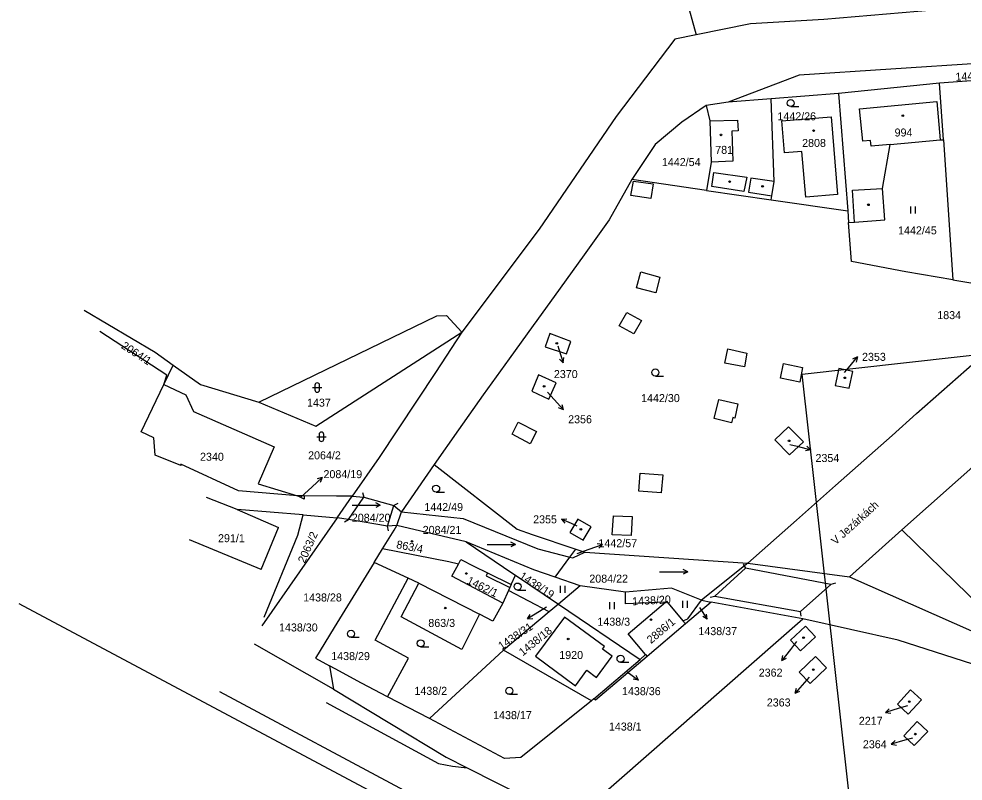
# Model space of a CAD drawing. Extents: x -794765 to -785424, y -1118958 to -1108731.
# Drawn here: x -792987.4 to -792786.8, y -1110324.3 to -1110162.4 of the extents above; entities that cross this region are included whole.
import ezdxf

# ---------------------------------------------------------------- set-up
doc = ezdxf.new("R2010")
doc.units = 0
for name, color, linetype in [('Level 66', 7, 'Continuous'), ('Level 71', 7, 'Continuous'), ('Level 75', 7, 'Continuous'), ('Level 76', 7, 'Continuous'), ('Level 77', 7, 'Continuous'), ('Level 79', 7, 'Continuous'), ('Level 80', 7, 'Continuous')]:
    doc.layers.add(name, color=color, linetype=linetype)

msp = doc.modelspace()

# ---------------------------------------------------------------- linework, layer by layer
at = {"layer": 'Level 66'}
for p, q in [((-792823.41, -1110181), (-792821.66, -1110181)), ((-792797.88, -1110203.74), (-792797.88, -1110202.24)), ((-792796.88, -1110203.74), (-792796.88, -1110202.24)), ((-792852.17, -1110238.22), (-792850.42, -1110238.22)), ((-792925.01, -1110240.68), (-792923.01, -1110240.68)), ((-792924.51, -1110240.18), (-792924.51, -1110241.18)), ((-792923.51, -1110241.18), (-792923.51, -1110240.18)), ((-792924.13, -1110251.13), (-792922.13, -1110251.13)), ((-792923.63, -1110250.63), (-792923.63, -1110251.63)), ((-792922.63, -1110251.63), (-792922.63, -1110250.63)), ((-792898.75, -1110262.89), (-792897, -1110262.89)), ((-792916.61, -1110265.68), (-792910.61, -1110265.68)), ((-792910.61, -1110265.68), (-792911.59, -1110265.18)), ((-792910.61, -1110265.68), (-792911.59, -1110266.18)), ((-792887.91, -1110274), (-792881.91, -1110274)), ((-792881.91, -1110274), (-792882.89, -1110273.5)), ((-792881.91, -1110274), (-792882.89, -1110274.5)), ((-792851.3, -1110279.84), (-792845.3, -1110279.84)), ((-792845.3, -1110279.84), (-792846.28, -1110279.34)), ((-792845.3, -1110279.84), (-792846.28, -1110280.34)), ((-792881.44, -1110283.69), (-792879.69, -1110283.69)), ((-792872.3, -1110284.28), (-792872.3, -1110282.78)), ((-792871.3, -1110284.28), (-792871.3, -1110282.78)), ((-792861.86, -1110287.77), (-792861.86, -1110286.27)), ((-792860.86, -1110287.77), (-792860.86, -1110286.27)), ((-792846.36, -1110287.47), (-792846.36, -1110285.97)), ((-792845.36, -1110287.47), (-792845.36, -1110285.97)), ((-792916.83, -1110293.72), (-792915.08, -1110293.72)), ((-792902.05, -1110295.76), (-792900.3, -1110295.76)), ((-792859.57, -1110299.03), (-792857.82, -1110299.03)), ((-792883.19, -1110305.83), (-792881.44, -1110305.83))]:
    msp.add_line(p, q, dxfattribs=at)
for centre in [(-792823.41, -1110180.25), (-792852.17, -1110237.47), (-792898.75, -1110262.14), (-792881.44, -1110282.94), (-792916.83, -1110292.97), (-792902.05, -1110295.01), (-792859.57, -1110298.28), (-792883.19, -1110305.08)]:
    msp.add_circle(centre, 0.75, dxfattribs=at)
for centre, start, end in [((-792924.01, -1110240.18), 0, 180), ((-792924.01, -1110241.18), 180, 359.9879), ((-792923.13, -1110250.63), 0, 180), ((-792923.13, -1110251.63), 180, 359.9879)]:
    msp.add_arc(centre, 0.5, start, end, dxfattribs=at)
at = {"layer": 'Level 71'}
msp.add_lwpolyline([(-792522.06, -1110204.41), (-792422.02, -1111099.6), (-792720.93, -1111133), (-792820.96, -1110237.81)], close=True, dxfattribs=at)
at = {"layer": 'Level 75'}
for p, q in [((-792845.9, -1110157.04), (-792843.51, -1110165.75)), ((-792765.3, -1110173.93), (-792791.78, -1110176.05)), ((-792791.78, -1110176.05), (-792813.29, -1110178.21)), ((-792790.97, -1110188.03), (-792791.78, -1110176.05)), ((-792827.55, -1110179.32), (-792836.73, -1110180.03)), ((-792813.29, -1110178.21), (-792827.55, -1110179.32)), ((-792813.29, -1110178.21), (-792811.29, -1110203.16)), ((-792836.73, -1110180.03), (-792841.38, -1110180.79)), ((-792790.97, -1110188.03), (-792788.97, -1110217.76)), ((-792841.32, -1110198.79), (-792857.15, -1110196.49)), ((-792841.32, -1110198.79), (-792827.6, -1110200.79)), ((-792827.6, -1110200.79), (-792811.29, -1110203.16)), ((-792811.29, -1110203.16), (-792811.1, -1110205.6)), ((-792788.97, -1110217.76), (-792768.39, -1110221.23)), ((-792973.54, -1110224.23), (-792958.48, -1110233.18)), ((-792958.48, -1110233.18), (-792954.6, -1110235.91)), ((-792956.62, -1110240.06), (-792954.6, -1110235.91)), ((-792954.6, -1110235.91), (-792948.79, -1110240.01)), ((-792956.62, -1110240.06), (-792951.92, -1110242.23)), ((-792948.79, -1110240.01), (-792936.43, -1110243.76)), ((-792769.54, -1110244.05), (-792799.79, -1110270.88)), ((-792899.17, -1110257.02), (-792906.12, -1110267.05)), ((-792926.76, -1110263.67), (-792928.23, -1110263.66)), ((-792919.79, -1110268.32), (-792916.57, -1110263.77)), ((-792907.12, -1110270), (-792906.12, -1110267.05)), ((-792919.79, -1110268.32), (-792935.78, -1110291.3)), ((-792892.36, -1110273.46), (-792907.12, -1110270)), ((-792810.95, -1110280.9), (-792799.79, -1110270.88)), ((-792911.93, -1110277.84), (-792910.16, -1110274.96)), ((-792870.31, -1110276.7), (-792869.04, -1110275)), ((-792869.04, -1110275), (-792867.13, -1110275.64)), ((-792867.13, -1110275.64), (-792832.52, -1110277.99)), ((-792904.66, -1110281.18), (-792911.93, -1110277.84)), ((-792873.47, -1110280.93), (-792870.31, -1110276.7)), ((-792832.52, -1110277.99), (-792842.37, -1110285.86)), ((-792832.52, -1110277.99), (-792810.95, -1110280.9)), ((-792882.78, -1110282.53), (-792881.86, -1110280.55)), ((-792881.86, -1110280.55), (-792872.78, -1110286.68)), ((-792868.13, -1110282.78), (-792873.47, -1110280.93)), ((-792883.35, -1110283.75), (-792884.61, -1110286.45)), ((-792874.76, -1110288.34), (-792883.35, -1110283.75)), ((-792868.13, -1110282.78), (-792872.78, -1110286.68)), ((-792858.5, -1110284.12), (-792868.13, -1110282.78)), ((-792840.31, -1110286.24), (-792845.77, -1110290.89)), ((-792842.37, -1110285.86), (-792840.31, -1110286.24)), ((-792820.87, -1110289.8), (-792840.31, -1110286.24)), ((-792872.78, -1110286.68), (-792874.76, -1110288.34)), ((-792872.78, -1110286.68), (-792855.41, -1110298.4)), ((-792874.76, -1110288.34), (-792884.46, -1110296.46)), ((-792845.77, -1110290.89), (-792846.34, -1110290.21)), ((-792845.77, -1110290.89), (-792853.89, -1110297.81)), ((-792920.52, -1110304.75), (-792937.34, -1110295.19)), ((-792924.39, -1110298.18), (-792921.42, -1110299.79)), ((-792884.46, -1110296.46), (-792900.15, -1110310.99)), ((-792865.76, -1110307.22), (-792884.46, -1110296.46)), ((-792853.89, -1110297.81), (-792864.87, -1110307.09)), ((-792855.41, -1110298.4), (-792854.27, -1110297.36)), ((-792854.27, -1110297.36), (-792853.89, -1110297.81)), ((-792921.42, -1110299.79), (-792920.52, -1110304.75)), ((-792865.22, -1110306.76), (-792855.41, -1110298.4)), ((-792900.15, -1110310.99), (-792909.06, -1110306.37)), ((-792865.22, -1110306.76), (-792865.76, -1110307.22)), ((-792864.87, -1110307.09), (-792865.22, -1110306.76))]:
    msp.add_line(p, q, dxfattribs=at)
for points in [[(-792793.11, -1110160.53), (-792816.41, -1110162.52), (-792831.95, -1110163.4), (-792843.51, -1110165.75)], [(-792843.51, -1110165.75), (-792848, -1110166.66), (-792860.5, -1110183.08), (-792876.83, -1110207.04), (-792893.29, -1110228.94)], [(-792724.21, -1110167.98), (-792821.65, -1110174.35), (-792836.73, -1110180.03)], [(-792827.6, -1110200.79), (-792827.45, -1110199.93), (-792826.92, -1110196.88), (-792827.55, -1110179.32)], [(-792841.38, -1110180.79), (-792846.53, -1110184.28), (-792852.19, -1110189.06), (-792857.15, -1110196.49)], [(-792841.38, -1110180.79), (-792840.6, -1110183.99), (-792840.3, -1110192.79), (-792841.32, -1110198.79)], [(-792813.45, -1110199.69), (-792820.2, -1110200.26), (-792821.03, -1110190.53), (-792824.71, -1110190.8), (-792825.3, -1110184.04), (-792814.83, -1110183.14), (-792813.45, -1110199.69)], [(-792811.1, -1110205.6), (-792809.89, -1110205.52), (-792803.4, -1110205.05), (-792803.88, -1110198.43), (-792802.3, -1110189.05), (-792791.66, -1110188.09), (-792790.97, -1110188.03)], [(-792857.15, -1110196.49), (-792861.96, -1110205.07), (-792867.33, -1110212.5), (-792872.43, -1110219.57), (-792877.35, -1110226.4), (-792878.15, -1110227.5), (-792883.23, -1110234.55), (-792888.74, -1110242.19), (-792893.98, -1110249.64), (-792899.17, -1110257.02)], [(-792788.97, -1110217.76), (-792798.95, -1110216.07), (-792810.47, -1110213.88), (-792811.1, -1110205.6)], [(-792832.52, -1110277.99), (-792822.21, -1110268.85), (-792813.91, -1110261.49), (-792801.89, -1110250.87), (-792796.66, -1110246.15), (-792768.39, -1110221.23)], [(-792936.43, -1110243.76), (-792898.61, -1110225.41), (-792896.52, -1110225.36), (-792893.29, -1110228.94)], [(-792956.62, -1110240.06), (-792955.98, -1110238.02), (-792970.23, -1110228.78)], [(-792936.43, -1110243.76), (-792924.34, -1110248.84), (-792893.29, -1110228.94)], [(-792893.29, -1110228.94), (-792898.91, -1110237.46), (-792910.83, -1110255.53), (-792916.57, -1110263.77)], [(-792874.62, -1110229.22), (-792875.6, -1110231.99), (-792871.07, -1110233.51), (-792870.1, -1110230.91), (-792874.62, -1110229.22)], [(-792874.8, -1110243.12), (-792873.23, -1110239.68), (-792876.98, -1110237.97), (-792878.45, -1110241.45), (-792874.8, -1110243.12)], [(-792813.99, -1110240.21), (-792811, -1110240.77), (-792810.21, -1110237.29), (-792813.21, -1110236.61), (-792813.99, -1110240.21)], [(-792928.23, -1110263.66), (-792940.73, -1110262.6), (-792953.02, -1110256.95), (-792953, -1110257.24), (-792958.43, -1110255.07), (-792958.74, -1110251.34), (-792961.42, -1110250.11), (-792956.62, -1110240.06)], [(-792951.92, -1110242.23), (-792950.31, -1110245.78), (-792933.18, -1110253.25), (-792936.55, -1110261.13), (-792928.23, -1110263.66)], [(-792823.85, -1110248.99), (-792826.77, -1110251.75), (-792823.7, -1110254.99), (-792820.68, -1110252.18), (-792823.85, -1110248.99)], [(-792899.17, -1110257.02), (-792881.53, -1110270.73), (-792878.38, -1110271.88), (-792869.04, -1110275)], [(-792927.02, -1110267.74), (-792941.03, -1110266.61), (-792947.55, -1110264.05)], [(-792926.76, -1110263.67), (-792926.8, -1110264.36), (-792928.23, -1110263.66)], [(-792916.57, -1110263.77), (-792919.91, -1110263.74), (-792926.76, -1110263.67)], [(-792916.57, -1110263.77), (-792914.11, -1110263.94), (-792907.75, -1110265.75), (-792906.12, -1110267.05)], [(-792935.32, -1110289.46), (-792928.14, -1110272.02), (-792927.02, -1110267.74)], [(-792927.02, -1110267.74), (-792921.4, -1110268.19), (-792919.79, -1110268.32)], [(-792906.12, -1110267.05), (-792893, -1110268.51), (-792877.11, -1110274.91), (-792870.31, -1110276.7)], [(-792907.12, -1110270), (-792909.08, -1110270.11), (-792917.38, -1110268.7), (-792919.79, -1110268.32)], [(-792910.16, -1110274.96), (-792907.69, -1110270.93), (-792907.12, -1110270)], [(-792867.49, -1110273.06), (-792865.84, -1110270.25), (-792868.65, -1110268.61), (-792870.36, -1110271.49), (-792867.49, -1110273.06)], [(-792799.79, -1110270.88), (-792785.68, -1110284.61), (-792780.46, -1110289.67), (-792774.1, -1110287.81), (-792768.98, -1110283.36), (-792748.68, -1110294.88)], [(-792892.36, -1110273.46), (-792882.45, -1110280.15), (-792881.86, -1110280.55)], [(-792873.47, -1110280.93), (-792877.98, -1110279.37), (-792892.36, -1110273.46)], [(-792894.02, -1110278.16), (-792896.04, -1110277.71), (-792910.16, -1110274.96)], [(-792870.31, -1110276.7), (-792869.7, -1110276.86), (-792867.13, -1110275.64)], [(-792911.93, -1110277.84), (-792920.4, -1110291.66), (-792924.39, -1110298.18)], [(-792884.61, -1110286.45), (-792895.4, -1110280.77), (-792894.02, -1110278.16)], [(-792894.02, -1110278.16), (-792893.53, -1110277.23), (-792890.72, -1110278.62), (-792887.81, -1110280.05), (-792882.78, -1110282.53)], [(-792909.06, -1110306.37), (-792904.65, -1110298.12), (-792911.69, -1110294.36), (-792904.66, -1110281.18)], [(-792884.61, -1110286.45), (-792886.72, -1110290.26), (-792889.5, -1110288.84), (-792893.29, -1110296.28), (-792896.99, -1110294.3), (-792906.21, -1110289.36), (-792902.39, -1110282.23), (-792904.66, -1110281.18)], [(-792810.95, -1110280.9), (-792780.07, -1110294.56), (-792755.03, -1110302.83), (-792738.35, -1110319.04), (-792720.66, -1110333.41), (-792681.61, -1110364.96), (-792649.52, -1110392.89)], [(-792882.78, -1110282.53), (-792883.08, -1110283.17), (-792883.35, -1110283.75)], [(-792850.04, -1110286.28), (-792858.54, -1110286.62), (-792858.5, -1110284.12)], [(-792842.37, -1110285.86), (-792848.73, -1110283.28), (-792858.5, -1110284.12)], [(-792854.27, -1110297.36), (-792857.96, -1110292.98), (-792850.04, -1110286.28)], [(-792850.04, -1110286.28), (-792849.81, -1110286.08), (-792846.34, -1110290.21)], [(-792846.34, -1110290.21), (-792845.29, -1110289.77), (-792842.37, -1110285.86)], [(-792987.4, -1110286.52), (-792903.63, -1110331.24), (-792901.83, -1110335.69)], [(-792863.41, -1110296.26), (-792863, -1110295.7), (-792871.48, -1110289.47), (-792877.63, -1110297.71), (-792869.11, -1110304.01), (-792866.7, -1110300.73)], [(-792861.96, -1110336.71), (-792864.51, -1110333.18), (-792865.03, -1110328.55), (-792820.87, -1110289.8)], [(-792614.4, -1110416.41), (-792624.78, -1110416.77), (-792634.65, -1110411.27), (-792666.12, -1110385.5), (-792684.9, -1110369.28), (-792739.95, -1110324.15), (-792759.16, -1110307.61), (-792800.59, -1110294.35), (-792820.87, -1110289.8)], [(-792821.33, -1110296.58), (-792818.18, -1110293.63), (-792820.28, -1110291.38), (-792823.43, -1110294.34), (-792821.33, -1110296.58)], [(-792866.7, -1110300.73), (-792864.66, -1110302.23), (-792861.37, -1110297.76), (-792863.41, -1110296.26)], [(-792819.27, -1110303.52), (-792815.84, -1110300.19), (-792818.18, -1110297.78), (-792821.61, -1110301.11), (-792819.27, -1110303.52)], [(-792909.06, -1110306.37), (-792914.61, -1110303.49), (-792920.21, -1110300.45), (-792921.42, -1110299.79)], [(-792920.52, -1110304.75), (-792896.6, -1110319.19), (-792892.13, -1110321.45), (-792866.5, -1110334.41), (-792861.96, -1110336.71)], [(-792795.65, -1110307), (-792797.95, -1110304.89), (-792800.73, -1110307.93), (-792798.43, -1110310.03), (-792795.65, -1110307)], [(-792865.76, -1110307.22), (-792880.76, -1110319.28), (-792884.2, -1110319.45), (-792900.15, -1110310.99)], [(-792794.31, -1110313.72), (-792796.53, -1110311.62), (-792799.38, -1110314.63), (-792797.16, -1110316.73), (-792794.31, -1110313.72)]]:
    msp.add_lwpolyline(points, dxfattribs=at)
at = {"layer": 'Level 77'}
for p, q in [((-792808.83, -1110181.45), (-792792.4, -1110179.95)), ((-792792.4, -1110179.95), (-792791.66, -1110188.09)), ((-792808.1, -1110188.37), (-792808.83, -1110181.45)), ((-792840.6, -1110183.99), (-792834.75, -1110183.87)), ((-792834.75, -1110183.87), (-792834.58, -1110186.16)), ((-792834.58, -1110186.16), (-792835.89, -1110186.25)), ((-792835.89, -1110186.25), (-792835.7, -1110192.61)), ((-792806.46, -1110188.19), (-792808.1, -1110188.37)), ((-792806.34, -1110189.41), (-792806.46, -1110188.19)), ((-792802.3, -1110189.05), (-792806.34, -1110189.41)), ((-792835.7, -1110192.61), (-792840.3, -1110192.79)), ((-792840.2, -1110197.95), (-792839.77, -1110194.99)), ((-792839.77, -1110194.99), (-792832.76, -1110196.02)), ((-792832.76, -1110196.02), (-792833.34, -1110199.02)), ((-792857.35, -1110199.89), (-792856.8, -1110196.81)), ((-792856.8, -1110196.81), (-792852.66, -1110197.4)), ((-792852.66, -1110197.4), (-792853.13, -1110200.52)), ((-792833.34, -1110199.02), (-792840.2, -1110197.95)), ((-792831.86, -1110196.19), (-792832.4, -1110199.16)), ((-792826.92, -1110196.88), (-792831.86, -1110196.19)), ((-792853.13, -1110200.52), (-792857.35, -1110199.89)), ((-792832.4, -1110199.16), (-792827.45, -1110199.93)), ((-792810.29, -1110198.78), (-792803.88, -1110198.43)), ((-792809.89, -1110205.52), (-792810.29, -1110198.78)), ((-792856.16, -1110219.49), (-792855.29, -1110216.11)), ((-792855.29, -1110216.11), (-792851.2, -1110217.2)), ((-792851.2, -1110217.2), (-792852.08, -1110220.56)), ((-792852.08, -1110220.56), (-792856.16, -1110219.49)), ((-792859.83, -1110227.54), (-792858.25, -1110224.71)), ((-792858.25, -1110224.71), (-792855.15, -1110226.43)), ((-792856.73, -1110229.27), (-792859.83, -1110227.54)), ((-792855.15, -1110226.43), (-792856.73, -1110229.27)), ((-792837.43, -1110235.48), (-792836.76, -1110232.44)), ((-792836.76, -1110232.44), (-792832.7, -1110233.35)), ((-792832.7, -1110233.35), (-792833.26, -1110236.25)), ((-792833.26, -1110236.25), (-792837.43, -1110235.48)), ((-792825.57, -1110238.69), (-792824.93, -1110235.56)), ((-792824.93, -1110235.56), (-792820.88, -1110236.41)), ((-792820.88, -1110236.41), (-792821.5, -1110239.52)), ((-792821.5, -1110239.52), (-792825.57, -1110238.69)), ((-792839.7, -1110247.27), (-792838.69, -1110243.18)), ((-792838.69, -1110243.18), (-792834.64, -1110244.14)), ((-792834.64, -1110244.14), (-792835.31, -1110247.16)), ((-792882.6, -1110250.56), (-792881.34, -1110248.01)), ((-792881.34, -1110248.01), (-792877.43, -1110250)), ((-792835.97, -1110248.19), (-792839.7, -1110247.27)), ((-792835.69, -1110247.06), (-792835.97, -1110248.19)), ((-792835.31, -1110247.16), (-792835.69, -1110247.06)), ((-792877.43, -1110250), (-792878.75, -1110252.61)), ((-792878.75, -1110252.61), (-792882.6, -1110250.56)), ((-792855.65, -1110262.71), (-792855.41, -1110258.83)), ((-792855.41, -1110258.83), (-792850.59, -1110259.23)), ((-792850.59, -1110259.23), (-792850.91, -1110263.04)), ((-792917.38, -1110268.7), (-792914.11, -1110263.94)), ((-792914.42, -1110262.99), (-792914.11, -1110263.94)), ((-792850.91, -1110263.04), (-792855.65, -1110262.71)), ((-792909.08, -1110270.11), (-792907.75, -1110265.75)), ((-792906.88, -1110265.27), (-792907.75, -1110265.75)), ((-792941.03, -1110266.61), (-792932.22, -1110270.38)), ((-792861.34, -1110271.93), (-792861.09, -1110267.89)), ((-792861.09, -1110267.89), (-792857.12, -1110268.09)), ((-792857.12, -1110268.09), (-792857.32, -1110272.1)), ((-792918.23, -1110269.23), (-792917.38, -1110268.7)), ((-792908.84, -1110271.08), (-792909.08, -1110270.11)), ((-792935.89, -1110279.29), (-792932.22, -1110270.38)), ((-792857.32, -1110272.1), (-792861.34, -1110271.93)), ((-792935.89, -1110279.29), (-792951.18, -1110272.99)), ((-792833.52, -1110278.2), (-792833, -1110279.06)), ((-792887.81, -1110280.05), (-792888.12, -1110280.67)), ((-792833, -1110279.06), (-792839.55, -1110285.01)), ((-792814.88, -1110282.54), (-792833, -1110279.06)), ((-792902.39, -1110282.23), (-792889.5, -1110288.84)), ((-792888.12, -1110280.67), (-792883.08, -1110283.17)), ((-792813.93, -1110282.22), (-792814.88, -1110282.54)), ((-792821.32, -1110288.22), (-792814.88, -1110282.54)), ((-792840.53, -1110285.22), (-792839.55, -1110285.01)), ((-792839.55, -1110285.01), (-792821.32, -1110288.22)), ((-792821.18, -1110289.21), (-792821.32, -1110288.22)), ((-792944.81, -1110305.21), (-792903.48, -1110327.29)), ((-792922.09, -1110307.54), (-792898.28, -1110320.5)), ((-792898.28, -1110320.5), (-792895.24, -1110321.1)), ((-792895.24, -1110321.1), (-792892.13, -1110321.45))]:
    msp.add_line(p, q, dxfattribs=at)
at = {"layer": 'Level 79'}
for centre in [(-792799.59, -1110182.93), (-792818.54, -1110186.11), (-792838.22, -1110187.01), (-792836.4, -1110196.93), (-792829.4, -1110197.95), (-792806.89, -1110201.86), (-792873.12, -1110231.28), (-792811.93, -1110238.61), (-792875.8, -1110240.43), (-792823.75, -1110251.99), (-792867.99, -1110270.79), (-792903.86, -1110273.34), (-792892.32, -1110280.17), (-792896.81, -1110287.5), (-792853.11, -1110289.97), (-792870.68, -1110294.08), (-792820.69, -1110293.81), (-792818.61, -1110300.58), (-792798.22, -1110307.39), (-792796.95, -1110314.29)]:
    msp.add_circle(centre, 0.175, dxfattribs=at)
at = {"layer": 'Level 80'}
for p, q in [((-792872.92, -1110231.83), (-792872.68, -1110232.55)), ((-792872.68, -1110232.55), (-792871.75, -1110235.4)), ((-792871.75, -1110235.4), (-792872.54, -1110234.61)), ((-792871.75, -1110235.4), (-792871.59, -1110234.3)), ((-792811.14, -1110236.49), (-792809.25, -1110234.16)), ((-792809.25, -1110234.16), (-792810.27, -1110234.62)), ((-792809.25, -1110234.16), (-792809.49, -1110235.25)), ((-792811.96, -1110237.5), (-792811.14, -1110236.49)), ((-792875.08, -1110241.63), (-792873.69, -1110243.19)), ((-792873.69, -1110243.19), (-792871.68, -1110245.42)), ((-792871.68, -1110245.42), (-792872.72, -1110245.01)), ((-792871.68, -1110245.42), (-792871.98, -1110244.34)), ((-792823.62, -1110252.74), (-792822.06, -1110253.14)), ((-792822.06, -1110253.14), (-792819.15, -1110253.87)), ((-792819.15, -1110253.87), (-792820.24, -1110254.11)), ((-792819.15, -1110253.87), (-792820, -1110253.14)), ((-792925.18, -1110261.82), (-792922.98, -1110259.77)), ((-792922.98, -1110259.77), (-792924.06, -1110260.09)), ((-792922.98, -1110259.77), (-792923.38, -1110260.82)), ((-792927.41, -1110263.89), (-792925.18, -1110261.82)), ((-792872.12, -1110268.66), (-792871.01, -1110268.59)), ((-792869.36, -1110269.83), (-792872.12, -1110268.66)), ((-792872.12, -1110268.66), (-792871.4, -1110269.51)), ((-792868.75, -1110270.08), (-792869.36, -1110269.83)), ((-792866.25, -1110275.03), (-792863.43, -1110274)), ((-792863.43, -1110274), (-792864.54, -1110273.88)), ((-792863.43, -1110274), (-792864.2, -1110274.82)), ((-792868.77, -1110275.95), (-792866.25, -1110275.03)), ((-792876.79, -1110288.23), (-792879.33, -1110289.82)), ((-792875.31, -1110287.31), (-792876.79, -1110288.23)), ((-792842.78, -1110287.38), (-792841.15, -1110289.9)), ((-792879.33, -1110289.82), (-792878.75, -1110288.86)), ((-792879.33, -1110289.82), (-792878.22, -1110289.71)), ((-792841.15, -1110289.9), (-792842.11, -1110289.33)), ((-792841.15, -1110289.9), (-792841.27, -1110288.78)), ((-792823.47, -1110296.29), (-792825.32, -1110298.66)), ((-792822.17, -1110294.61), (-792823.47, -1110296.29)), ((-792825.32, -1110298.66), (-792825.1, -1110297.56)), ((-792825.32, -1110298.66), (-792824.31, -1110298.17)), ((-792858.17, -1110301.04), (-792855.77, -1110302.85)), ((-792855.77, -1110302.85), (-792856.27, -1110301.84)), ((-792819.5, -1110302.17), (-792820.51, -1110303.32)), ((-792855.77, -1110302.85), (-792856.87, -1110302.64)), ((-792820.51, -1110303.32), (-792822.48, -1110305.58)), ((-792822.48, -1110305.58), (-792822.2, -1110304.5)), ((-792822.48, -1110305.58), (-792821.44, -1110305.16)), ((-792798.63, -1110308.25), (-792800.4, -1110308.79)), ((-792800.4, -1110308.79), (-792803.27, -1110309.67)), ((-792803.27, -1110309.67), (-792802.46, -1110308.9)), ((-792803.27, -1110309.67), (-792802.17, -1110309.85)), ((-792799.19, -1110315.6), (-792802.08, -1110316.43)), ((-792802.08, -1110316.43), (-792801.25, -1110315.67)), ((-792797.52, -1110315.11), (-792799.19, -1110315.6)), ((-792802.08, -1110316.43), (-792800.97, -1110316.63))]:
    msp.add_line(p, q, dxfattribs=at)

# ---------------------------------------------------------------- texts
at = {"layer": 'Level 76'}
for s, rotation, p in [('1442/51', 3, (-792788.36, -1110175.52)), ('2064/1', 327, (-792965.79, -1110232.21)), ('2063/2', 66, (-792926.66, -1110278.11)), ('863/4', 349, (-792907.3, -1110274.77)), ('1438/19', 327, (-792881.25, -1110281.12)), ('1462/1', 334, (-792892.38, -1110282.23)), ('1438/20', 3, (-792857.05, -1110286.93)), ('2886/1', 40, (-792853.1, -1110295.18)), ('1438/31', 34, (-792884.84, -1110296.46)), ('1438/18', 39, (-792880.33, -1110297.78))]:
    msp.add_text(s, height=1.7, rotation=rotation, dxfattribs=at).set_placement(p)
for s, p in [('1442/26', (-792826.24, -1110183.91)), ('994', (-792801.34, -1110187.35)), ('2808', (-792820.99, -1110189.57)), ('781', (-792839.45, -1110191.04)), ('1442/54', (-792850.78, -1110193.63)), ('1442/45', (-792800.6, -1110208.14)), ('1834', (-792792.28, -1110226.14)), ('2353', (-792808.26, -1110235)), ('2370', (-792873.73, -1110238.66)), ('1442/30', (-792855.2, -1110243.76)), ('1437', (-792926.18, -1110244.73)), ('2356', (-792870.7, -1110248.26)), ('2064/2', (-792925.95, -1110255.92)), ('2340', (-792948.91, -1110256.22)), ('2354', (-792818.15, -1110256.49)), ('2084/19', (-792922.68, -1110259.92)), ('1442/49', (-792901.25, -1110266.9)), ('2084/20', (-792916.66, -1110269.17)), ('2355', (-792878.14, -1110269.52)), ('2084/21', (-792901.6, -1110271.76)), ('291/1', (-792945.09, -1110273.52)), ('1442/57', (-792864.26, -1110274.58)), ('2084/22', (-792866.2, -1110282.11)), ('1438/28', (-792927, -1110286.11)), ('863/3', (-792900.41, -1110291.52)), ('1438/3', (-792864.49, -1110291.26)), ('1438/30', (-792932.13, -1110292.48)), ('1438/37', (-792843.03, -1110293.26)), ('1438/29', (-792921.04, -1110298.56)), ('1920', (-792872.59, -1110298.33)), ('2362', (-792830.21, -1110302.07)), ('1438/2', (-792903.36, -1110305.94)), ('1438/36', (-792859.26, -1110306.01)), ('2363', (-792828.5, -1110308.41)), ('1438/17', (-792886.64, -1110311.1)), ('1438/1', (-792862.04, -1110313.53)), ('2217', (-792808.94, -1110312.31)), ('2364', (-792808.08, -1110317.29))]:
    msp.add_text(s, height=1.7, dxfattribs=at).set_placement(p)
at = {"layer": 'Level 80'}
msp.add_text('V Jezárkách', height=1.7, rotation=42, dxfattribs=at).set_placement((-792813.87, -1110274.2))

doc.saveas('drawing.dxf')
